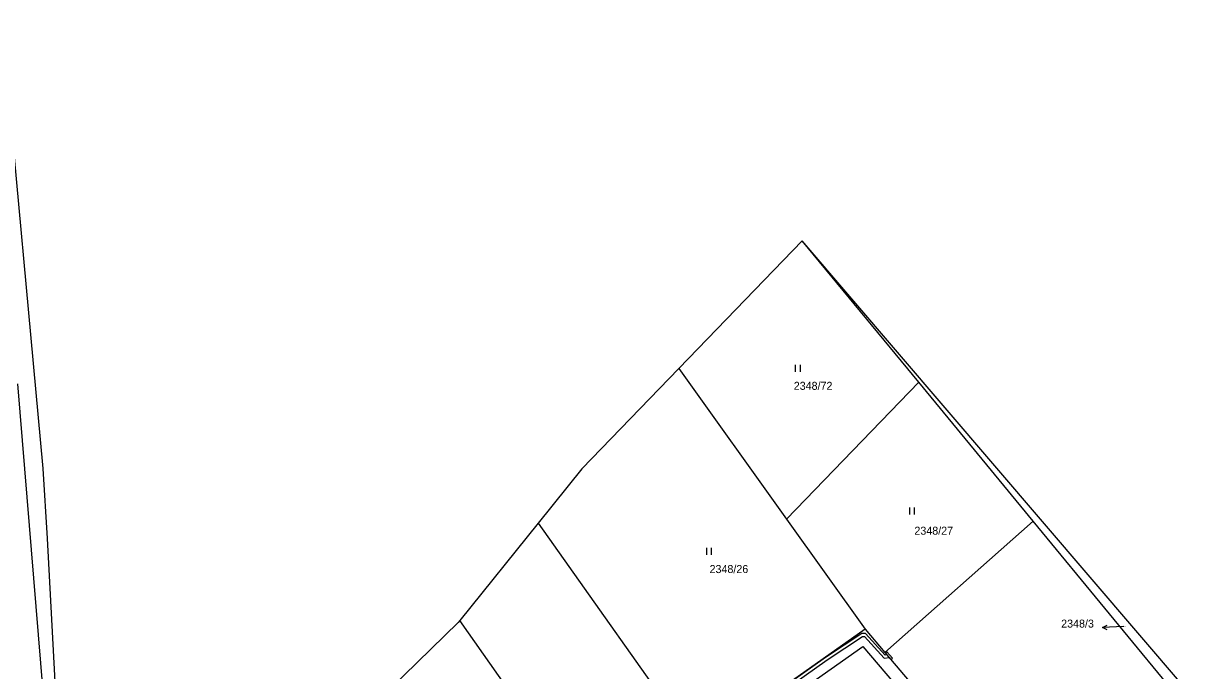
# Model space of a CAD drawing. Extents: x -785744 to -782822, y -1067550 to -1063910.
# Drawn here: x -783398.4 to -783151.5, y -1066667 to -1066529.4 of the extents above; entities that cross this region are included whole.
import ezdxf

# ---------------------------------------------------------------- set-up
doc = ezdxf.new("R2010")
doc.units = 0
for name, color, linetype in [('Hranice kat_území', 7, 'Continuous'), ('Hranice parcel', 7, 'Continuous'), ('Parcelní čísla', 7, 'Continuous'), ('Pop_ČP_popisy', 7, 'Continuous'), ('Vnitřní kresba', 7, 'Continuous'), ('Věcná břemena k části', 7, 'Continuous'), ('Značky kultur', 7, 'Continuous')]:
    doc.layers.add(name, color=color, linetype=linetype)

msp = doc.modelspace()

# ---------------------------------------------------------------- linework, layer by layer
at = {"layer": 'Hranice kat_území'}
for points in [[(-783389.1, -1066715.67), (-783393.21, -1066638.91), (-783394.16, -1066624.03), (-783402.86, -1066529.41)], [(-783151.52, -1066670.79), (-783232.95, -1066575.65), (-783259.18, -1066602.79), (-783279.76, -1066624.09), (-783289.03, -1066635.63), (-783305.68, -1066656.36), (-783306.02, -1066656.78), (-783326.3, -1066676.53)]]:
    msp.add_lwpolyline(points, dxfattribs=at)
at = {"layer": 'Hranice parcel'}
for p, q in [((-783208.19, -1066605.72), (-783232.95, -1066575.65)), ((-783259.18, -1066602.79), (-783236.29, -1066634.81)), ((-783236.29, -1066634.81), (-783208.19, -1066605.72)), ((-783183.91, -1066635.22), (-783208.19, -1066605.72)), ((-783236.29, -1066634.81), (-783219.6, -1066658.16)), ((-783276.13, -1066698.11), (-783305.68, -1066656.36))]:
    msp.add_line(p, q, dxfattribs=at)
for points in [[(-783289.03, -1066635.63), (-783255.28, -1066683.38)], [(-783215.38, -1066663.14), (-783183.91, -1066635.22)], [(-783151.5, -1066674.6), (-783183.91, -1066635.22)], [(-783219.6, -1066658.16), (-783255.28, -1066683.38)], [(-783219.6, -1066658.16), (-783215.38, -1066663.14)], [(-783253.69, -1066685.62), (-783220.07, -1066661.86)], [(-783220.07, -1066661.86), (-783173.25, -1066716.89)], [(-783215.38, -1066663.14), (-783170.89, -1066715.62)]]:
    msp.add_lwpolyline(points, dxfattribs=at)
at = {"layer": 'Pop_ČP_popisy'}
msp.add_line((-783166.2, -1066657.71), (-783169.2, -1066657.85), dxfattribs=at)
for points in [[(-783168.17, -1066658.3), (-783169.2, -1066657.85), (-783168.22, -1066657.3)], [(-783164.62, -1066657.64), (-783166.2, -1066657.71)]]:
    msp.add_lwpolyline(points, dxfattribs=at)
at = {"layer": 'Vnitřní kresba'}
msp.add_lwpolyline([(-783399.57, -1066606.07), (-783394.24, -1066671.45)], dxfattribs=at)
at = {"layer": 'Věcná břemena k části'}
for points in [[(-783220.32, -1066659.11), (-783228.01, -1066664.2)], [(-783227.67, -1066664.7), (-783220.14, -1066659.71)], [(-783219.48, -1066659.13), (-783220.32, -1066659.11)], [(-783220.14, -1066659.71), (-783219.74, -1066659.73)], [(-783219.74, -1066659.73), (-783215.57, -1066664.33)], [(-783215.33, -1066663.69), (-783219.48, -1066659.13)], [(-783228.01, -1066664.2), (-783249.74, -1066679.65)], [(-783249.4, -1066680.13), (-783227.67, -1066664.7)], [(-783215.57, -1066664.33), (-783214.5, -1066664.18)], [(-783214.96, -1066663.64), (-783215.33, -1066663.69)], [(-783214.96, -1066663.02), (-783215.26, -1066663.28)], [(-783215.26, -1066663.28), (-783214.96, -1066663.64)], [(-783213.8, -1066664.37), (-783214.96, -1066663.02)], [(-783214.5, -1066664.18), (-783214.11, -1066664.64)], [(-783214.11, -1066664.64), (-783213.8, -1066664.37)]]:
    msp.add_lwpolyline(points, dxfattribs=at)
at = {"layer": 'Značky kultur'}
for p, q in [((-783234.35, -1066603.5), (-783234.35, -1066602)), ((-783233.35, -1066603.5), (-783233.35, -1066602)), ((-783210.08, -1066633.84), (-783210.08, -1066632.34)), ((-783209.08, -1066633.84), (-783209.08, -1066632.34)), ((-783253.23, -1066642.38), (-783253.23, -1066640.88)), ((-783252.23, -1066642.38), (-783252.23, -1066640.88))]:
    msp.add_line(p, q, dxfattribs=at)

# ---------------------------------------------------------------- texts
at = {"layer": 'Parcelní čísla'}
for s, height, p in [('2348/72', 1.7, (-783234.75, -1066607.32)), ('2348/27', 1.7, (-783209.13, -1066638.11)), ('2348/26', 1.7, (-783252.63, -1066646.26)), ('2348/3', 0.1, (-783164.62, -1066657.64))]:
    msp.add_text(s, height=height, dxfattribs=at).set_placement(p)
at = {"layer": 'Pop_ČP_popisy'}
msp.add_text('2348/3', height=1.7, dxfattribs=at).set_placement((-783177.96, -1066657.85))

doc.saveas('drawing.dxf')
